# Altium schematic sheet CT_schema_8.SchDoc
size 209 x 185 mm
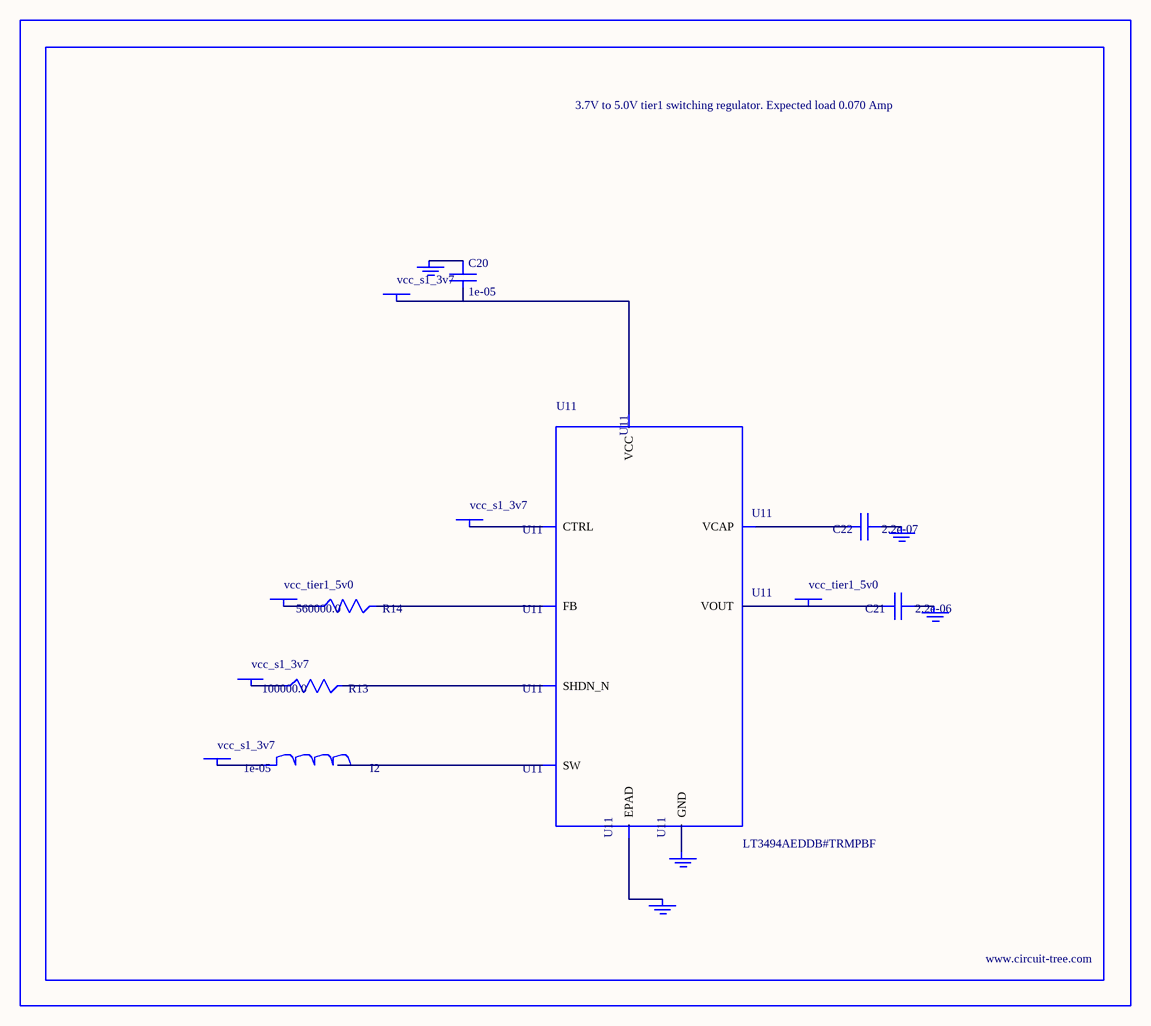
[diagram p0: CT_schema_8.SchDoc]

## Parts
BORDER7  (no value)
C20  1e-05  [C1210]
C21  2.2e-06  [C0603]
C22  2.2e-07  [C0603]
GND_INSTANCE_7_0  (no value)
GND_INSTANCE_7_1  (no value)
GND_INSTANCE_7_2  (no value)
GND_INSTANCE_7_3  (no value)
GND_INSTANCE_7_4  (no value)
I2  1e-05  [L1210]
POWER_INSTANCE_7_0  vcc_s1_3v7
POWER_INSTANCE_7_1  vcc_s1_3v7
POWER_INSTANCE_7_2  vcc_s1_3v7
POWER_INSTANCE_7_3  vcc_s1_3v7
POWER_INSTANCE_7_4  vcc_tier1_5v0
POWER_INSTANCE_7_5  vcc_tier1_5v0
R13  100000.0  [R0603]
R14  560000.0  [R0603]
U11  LT3494AEDDB#TRMPBF  [DFN-8_DDB]

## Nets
NetC20_1: C20.1 GND_INSTANCE_7_0.0(GND)
NetC20_2: C20.2 POWER_INSTANCE_7_1.0(PWR) U11.3(VCC)
NetC21_1: C21.1 GND_INSTANCE_7_1.0(GND)
NetC21_2: C21.2 POWER_INSTANCE_7_5.0(PWR) U11.7(VOUT)
NetC22_1: C22.1 GND_INSTANCE_7_2.0(GND)
NetC22_2: C22.2 U11.8(VCAP)
NetGND_INSTANCE_7_3_0: GND_INSTANCE_7_3.0(GND) U11.9(EPAD)
NetGND_INSTANCE_7_4_0: GND_INSTANCE_7_4.0(GND) U11.2(GND)
NetI2_1: I2.1 POWER_INSTANCE_7_0.0(PWR)
NetI2_2: I2.2 U11.1(SW)
NetPOWER_INSTANCE_7_2_0: POWER_INSTANCE_7_2.0(PWR) U11.4(CTRL)
NetPOWER_INSTANCE_7_3_0: POWER_INSTANCE_7_3.0(PWR) R13.1
NetPOWER_INSTANCE_7_4_0: POWER_INSTANCE_7_4.0(PWR) R14.1
NetR13_2: R13.2 U11.5(SHDN_N)
NetR14_2: R14.2 U11.6(FB)

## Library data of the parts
BORDER7 = BORDER_PAGE7
C20 = C1210C106K5PACTU
C21 = GRM188R61H225KE1115D
C22 = C0603C224K3RAC
GND_INSTANCE_7_0-GND_INSTANCE_7_4 = GND
I2 = CBC3225T100MR
POWER_INSTANCE_7_0-POWER_INSTANCE_7_5 = PWR
R13 = RC0603JR-07100KL
R14 = RC0603JR-07560KL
